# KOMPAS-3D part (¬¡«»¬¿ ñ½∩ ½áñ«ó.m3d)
File: created 15.08.2015 13:49:15, last saved 03.09.2015 11:30:06.
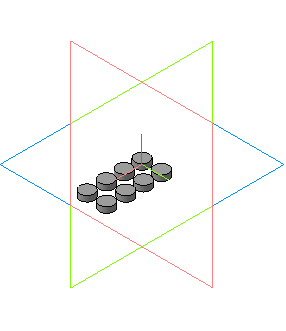
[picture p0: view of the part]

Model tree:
1. Эскиз:1
2. Операция выдавливания:1
     Расстояние 1 = 2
